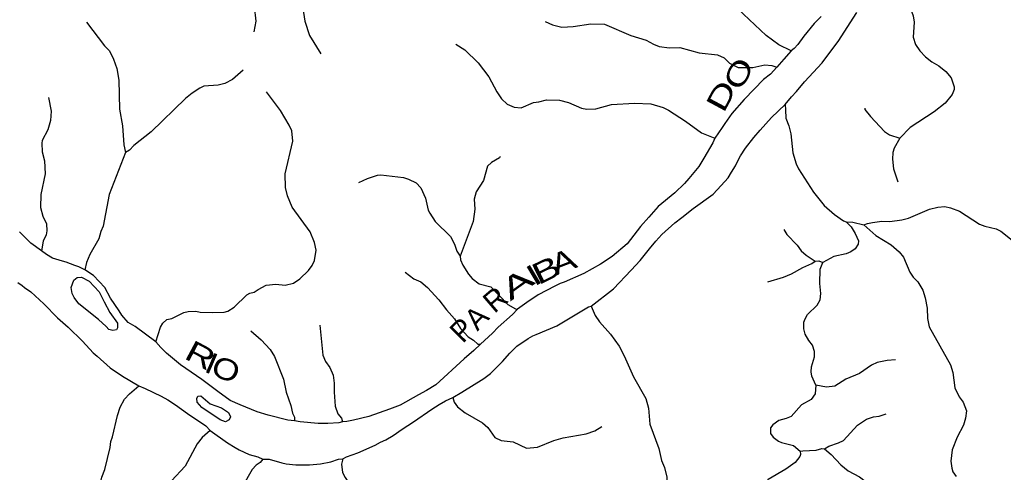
# Model space of a CAD drawing. Extents: x 577 to 602.9, y 7483.8 to 7511.6.
# Drawn here: x 584.92 to 589.586, y 7506.321 to 7508.468 of the extents above; entities that cross this region are included whole.
import ezdxf
from ezdxf.enums import TextEntityAlignment as Align

# ---------------------------------------------------------------- set-up
doc = ezdxf.new("R2010")
doc.units = 0
doc.header["$LTSCALE"] = 0.032
doc.layers.add('2', color=7, linetype='Continuous', lineweight=25)
doc.layers.add('7', color=7, linetype='Continuous', lineweight=25)
doc.layers.add('61', color=7, linetype='Continuous')

msp = doc.modelspace()

# ---------------------------------------------------------------- linework, layer by layer
at = {"layer": '2'}
for points in [[(588.7211, 7508.483), (588.6892, 7508.4503), (588.6402, 7508.3898), (588.6107, 7508.3505), (588.5936, 7508.3309), (588.5797, 7508.3203), (588.5453, 7508.2802), (588.511, 7508.2435), (588.4808, 7508.2091), (588.4489, 7508.1838), (588.4031, 7508.138), (588.3565, 7508.0898), (588.2977, 7508.0236), (588.2642, 7507.9762), (588.2519, 7507.9565), (588.2167, 7507.9059), (588.2077, 7507.8846), (588.1644, 7507.8119), (588.1407, 7507.7718), (588.0933, 7507.7146), (588.0729, 7507.6909), (588.0279, 7507.6476), (587.9486, 7507.5814), (587.9037, 7507.5315), (587.8653, 7507.4865), (587.8015, 7507.4048), (587.7296, 7507.3451), (587.6756, 7507.3092), (587.5963, 7507.265), (587.5031, 7507.2225), (587.4843, 7507.2168), (587.459, 7507.2037), (587.3797, 7507.1637), (587.325, 7507.1269), (587.2808, 7507.0958), (587.2579, 7507.0697), (587.1893, 7507.01), (587.1623, 7506.9814), (587.1051, 7506.9291), (587.0748, 7506.8996), (587.029, 7506.8596), (586.8934, 7506.737), (586.8492, 7506.71), (586.8116, 7506.6896), (586.725, 7506.6405), (586.6743, 7506.6209), (586.5762, 7506.5866), (586.5035, 7506.5686), (586.4724, 7506.562), (586.4511, 7506.5612), (586.434, 7506.5563), (586.3825, 7506.5522), (586.3359, 7506.5522), (586.2509, 7506.5604), (586.2239, 7506.5661), (586.192, 7506.5686), (586.0988, 7506.5931), (586.0473, 7506.6086), (585.9664, 7506.6422), (585.919, 7506.6626), (585.8602, 7506.7043), (585.8283, 7506.728), (585.7841, 7506.7623), (585.6828, 7506.831), (585.6166, 7506.8857), (585.5896, 7506.9127), (585.5667, 7506.9405), (585.4686, 7507.0124), (585.4351, 7507.0312), (585.404, 7507.0672), (585.3918, 7507.0868), (585.3509, 7507.1473), (585.3248, 7507.198), (585.2708, 7507.2552), (585.2299, 7507.2822), (585.2005, 7507.2953), (585.1825, 7507.3018), (585.14, 7507.3181), (585.1229, 7507.3231), (585.0763, 7507.3378), (585.0468, 7507.3541), (585.0239, 7507.3721), (584.9733, 7507.4081), (584.9185, 7507.4612)], [(586.2304, 7506.3569), (586.2942, 7506.3561), (586.3473, 7506.361), (586.3964, 7506.3716), (586.4323, 7506.3839), (586.4528, 7506.3847), (586.4699, 7506.3953), (586.5247, 7506.4133), (586.6064, 7506.4501), (586.6318, 7506.464), (586.6563, 7506.4754), (586.6923, 7506.4958), (586.734, 7506.5261), (586.7887, 7506.5612), (586.8754, 7506.6201), (586.9105, 7506.643), (586.94, 7506.6601), (586.9751, 7506.6757), (587.0168, 7506.7018), (587.1222, 7506.7664), (587.1533, 7506.7901), (587.2097, 7506.8465), (587.2448, 7506.8857), (587.2784, 7506.9193), (587.3315, 7506.956), (587.3544, 7506.9683), (587.3699, 7506.9748), (587.4672, 7507.0163), (587.6176, 7507.1064), (587.6307, 7507.1097), (587.7361, 7507.1923), (587.8211, 7507.2805), (587.8636, 7507.3263), (587.9078, 7507.3819), (587.9372, 7507.4179), (587.9658, 7507.4489), (588.0279, 7507.5045), (588.0606, 7507.5299), (588.1146, 7507.5724), (588.2094, 7507.6402), (588.2478, 7507.6811), (588.2813, 7507.7179), (588.2968, 7507.7448), (588.3148, 7507.7743), (588.3263, 7507.7988), (588.3394, 7507.8217), (588.3622, 7507.8585), (588.4023, 7507.91), (588.4317, 7507.9443), (588.4865, 7508.0048), (588.5516, 7508.066), (588.5813, 7508.102), (588.6043, 7508.1276), (588.6426, 7508.174), (588.7268, 7508.2639), (588.7489, 7508.2941), (588.8028, 7508.3652), (588.8903, 7508.5018)], [(584.9118, 7507.2219), (584.9314, 7507.2071), (584.9426, 7507.1973), (584.9725, 7507.1776), (585.0346, 7507.1203), (585.0992, 7507.0541), (585.1498, 7507.01), (585.2185, 7506.943), (585.2684, 7506.8882), (585.2872, 7506.8718), (585.3501, 7506.8163), (585.4081, 7506.777), (585.4852, 7506.7311), (585.5148, 7506.7183), (585.592, 7506.683), (585.6223, 7506.665), (585.6591, 7506.6413), (585.7163, 7506.5996), (585.8038, 7506.5416), (585.8234, 7506.5204), (585.9051, 7506.4607), (585.9427, 7506.4386), (585.9607, 7506.4272), (586.0089, 7506.4059), (586.049, 7506.3953), (586.0727, 7506.3839), (586.1037, 7506.383), (586.1634, 7506.3667), (586.1847, 7506.361), (586.2304, 7506.3569)]]:
    msp.add_lwpolyline(points, dxfattribs=at)
for points in [[(585.1784, 7507.1498), (585.1686, 7507.1702), (585.1645, 7507.198), (585.1768, 7507.2323), (585.1932, 7507.2446), (585.2136, 7507.2462), (585.2496, 7507.2282), (585.2978, 7507.1767), (585.3215, 7507.1301), (585.3476, 7507.0786), (585.3836, 7507.028), (585.3844, 7507.0059), (585.3795, 7506.9977), (585.3615, 7506.9936), (585.3436, 7506.9985), (585.3305, 7507.0133), (585.2945, 7507.046), (585.2013, 7507.1203)], [(585.8781, 7506.6274), (585.91, 7506.6054), (585.9198, 7506.5849), (585.9141, 7506.571), (585.8969, 7506.5612), (585.8716, 7506.5702), (585.7843, 7506.6286), (585.7627, 7506.6534), (585.7601, 7506.6712), (585.7646, 7506.6833), (585.7793, 7506.6839), (585.8234, 7506.6462)]]:
    msp.add_lwpolyline(points, close=True, dxfattribs=at)
at = {"layer": '7'}
for points in [[(588.5797, 7508.3203), (588.5208, 7508.3481), (588.4611, 7508.393), (588.3001, 7508.5443), (588.2454, 7508.5761), (588.2045, 7508.5859), (588.162, 7508.6039), (588.1334, 7508.6342), (588.1268, 7508.6546), (588.1072, 7508.6898), (588.086, 7508.7086), (588.0484, 7508.7331), (588.023, 7508.7601), (587.9952, 7508.8009)], [(586.2631, 7508.7061), (586.2656, 7508.6963), (586.2631, 7508.5884), (586.2582, 7508.5524), (586.2721, 7508.4609), (586.2942, 7508.3939), (586.3478, 7508.3065)], [(589.0212, 7508.7066), (589.026, 7508.6742), (589.0391, 7508.6383), (589.1175, 7508.5622), (589.142, 7508.5295), (589.1584, 7508.4862), (589.1633, 7508.456), (589.1584, 7508.3857), (589.169, 7508.3505), (589.1895, 7508.3203), (589.2164, 7508.2917), (589.2467, 7508.2688), (589.2802, 7508.25), (589.3137, 7508.223), (589.3382, 7508.1928), (589.3529, 7508.1495), (589.3521, 7508.1364), (589.3431, 7508.1135), (589.3104, 7508.0718), (589.2581, 7508.0309), (589.1437, 7507.9574), (589.0946, 7507.9067)], [(586.0866, 7508.675), (586.0792, 7508.6579), (586.0596, 7508.6358), (586.0482, 7508.6146), (586.0367, 7508.572), (586.0326, 7508.5304), (586.0408, 7508.4617), (586.0302, 7508.4109)], [(585.2374, 7508.4571), (585.3223, 7508.3448), (585.346, 7508.3203), (585.3656, 7508.2802), (585.3803, 7508.2369), (585.391, 7508.1813), (585.3934, 7508.044), (585.4081, 7507.9647), (585.4147, 7507.874), (585.422, 7507.8388)], [(587.4121, 7508.46), (587.4476, 7508.4437), (587.4909, 7508.4331), (587.5448, 7508.4355), (587.629, 7508.4478), (587.6944, 7508.4462), (587.8187, 7508.3939), (587.8922, 7508.371), (587.9266, 7508.3513), (587.9527, 7508.3415), (588.0018, 7508.335), (588.0516, 7508.3358), (588.1424, 7508.3105), (588.2298, 7508.3007), (588.2609, 7508.2876), (588.2869, 7508.2615), (588.3276, 7508.242), (588.3982, 7508.2418), (588.4546, 7508.2533), (588.4881, 7508.2516), (588.511, 7508.2435)], [(586.9884, 7508.3525), (587.0315, 7508.3244), (587.0953, 7508.2631), (587.1459, 7508.1977), (587.1835, 7508.1257), (587.2048, 7508.093), (587.2318, 7508.0669), (587.2661, 7508.0538), (587.298, 7508.0505), (587.3568, 7508.0751), (587.3822, 7508.0792), (587.4181, 7508.0873), (587.4811, 7508.0857), (587.5228, 7508.0759), (587.5849, 7508.0481), (587.6094, 7508.044), (587.6535, 7508.0456), (587.7271, 7508.0661), (587.8366, 7508.0726), (587.9135, 7508.0685), (587.9715, 7508.0522), (587.9977, 7508.0391), (588.0786, 7507.9868), (588.1546, 7507.9312), (588.2167, 7507.9059)], [(585.9798, 7508.2282), (585.9288, 7508.1838), (585.8937, 7508.1658), (585.861, 7508.1576), (585.7939, 7508.1527), (585.7743, 7508.1437), (585.7384, 7508.1192), (585.7073, 7508.0947), (585.5438, 7507.9361), (585.4621, 7507.8707), (585.4408, 7507.8495), (585.422, 7507.8388)], [(585.0567, 7508.0987), (585.0689, 7508.035), (585.0665, 7507.9892), (585.0534, 7507.9459), (585.0264, 7507.8944), (585.0256, 7507.8822), (585.0272, 7507.8421), (585.0378, 7507.798), (585.0403, 7507.7367), (585.0207, 7507.6394), (585.019, 7507.5773), (585.0305, 7507.5356), (585.0468, 7507.4996), (585.0485, 7507.4669), (585.0452, 7507.4481), (585.0313, 7507.4171), (585.0239, 7507.3721)], [(585.5667, 7506.9405), (585.588, 7507.0092), (585.5986, 7507.028), (585.6182, 7507.046), (585.6411, 7507.0509), (585.6991, 7507.0795), (585.7196, 7507.0844), (585.7555, 7507.086), (585.776, 7507.0811), (585.8332, 7507.0786), (585.8904, 7507.0803), (585.9067, 7507.0852), (585.9378, 7507.104), (585.9983, 7507.1637), (586.0122, 7507.1718), (586.0326, 7507.1751), (586.0514, 7507.189), (586.0898, 7507.2086), (586.1348, 7507.2135), (586.1798, 7507.2086), (586.219, 7507.2184), (586.2492, 7507.2397), (586.2901, 7507.2781), (586.3073, 7507.3018), (586.3187, 7507.3255), (586.3269, 7507.3745), (586.3187, 7507.4121), (586.2975, 7507.462), (586.2125, 7507.5797), (586.1904, 7507.6328), (586.1814, 7507.6721), (586.1798, 7507.7375), (586.2165, 7507.892), (586.2108, 7507.941), (586.1986, 7507.968), (586.1569, 7508.0375), (586.0908, 7508.1253)], [(588.5516, 7508.066), (588.5519, 7508.0407), (588.5535, 7508.0015), (588.5682, 7507.9647), (588.578, 7507.9271), (588.5878, 7507.8372), (588.6026, 7507.7841), (588.614, 7507.7604), (588.6859, 7507.65), (588.7366, 7507.5871), (588.7848, 7507.5438), (588.8273, 7507.5135), (588.8396, 7507.5086)], [(588.9286, 7508.0481), (588.9295, 7508.0416), (588.9549, 7508.0089), (589.0219, 7507.9377), (589.0456, 7507.9214), (589.0946, 7507.9067)], [(589.0946, 7507.9067), (589.0677, 7507.8593), (589.0619, 7507.838), (589.0595, 7507.807), (589.0644, 7507.7604), (589.0853, 7507.6985)], [(585.422, 7507.8388), (585.3452, 7507.6386), (585.3166, 7507.489), (585.3051, 7507.4636), (585.2953, 7507.4285), (585.2534, 7507.3548), (585.237, 7507.3165), (585.2299, 7507.2822)], [(587.1992, 7507.8196), (587.1966, 7507.8135), (587.1574, 7507.7914), (587.1386, 7507.7734), (587.1198, 7507.7056), (587.0846, 7507.6516), (587.0756, 7507.6165), (587.0797, 7507.5699), (587.0707, 7507.5111), (587.0094, 7507.3468)], [(586.5284, 7507.6964), (586.5697, 7507.7154), (586.6171, 7507.7309), (586.6334, 7507.7318), (586.7405, 7507.7203), (586.765, 7507.7121), (586.801, 7507.6942), (586.8222, 7507.6704), (586.8451, 7507.6214), (586.8582, 7507.5642), (586.8656, 7507.5503), (586.8909, 7507.5111), (586.9637, 7507.4391), (586.9825, 7507.404), (586.9939, 7507.3705), (587.0094, 7507.3468)], [(588.9246, 7507.4947), (588.941, 7507.5021), (588.9647, 7507.5062), (589.0096, 7507.5119), (589.0472, 7507.5111), (589.1036, 7507.5184), (589.1355, 7507.5266), (589.2352, 7507.5691), (589.2745, 7507.5797), (589.3088, 7507.5814), (589.335, 7507.5764), (589.3783, 7507.5601), (589.4731, 7507.498), (589.4984, 7507.4882), (589.5524, 7507.4759), (589.5736, 7507.4653), (589.6276, 7507.422), (589.6725, 7507.3721), (589.6979, 7507.35), (589.7759, 7507.3057)], [(588.8396, 7507.5086), (588.8641, 7507.4857), (588.8837, 7507.4538), (588.8985, 7507.4187), (588.8976, 7507.404), (588.8829, 7507.3819), (588.8625, 7507.3672), (588.8396, 7507.3574), (588.7824, 7507.3443), (588.7301, 7507.3165)], [(588.8396, 7507.5086), (588.8715, 7507.507), (588.9246, 7507.4947)], [(588.9246, 7507.4947), (588.9802, 7507.4448), (589.0538, 7507.3999), (589.0922, 7507.3664), (589.1118, 7507.3419), (589.142, 7507.2707), (589.1584, 7507.2462), (589.1796, 7507.2241), (589.2042, 7507.1849), (589.2156, 7507.1489), (589.2238, 7507.0999), (589.2254, 7507.0509), (589.2336, 7507.0108), (589.335, 7506.8318), (589.3464, 7506.7942), (589.3562, 7506.7214), (589.3766, 7506.6798), (589.3946, 7506.6544), (589.411, 7506.6127), (589.4069, 7506.5784), (589.3971, 7506.5457), (589.3668, 7506.4877), (589.3431, 7506.428), (589.3366, 7506.3749), (589.3407, 7506.3413), (589.3464, 7506.3242), (589.3619, 7506.3021)], [(588.5441, 7507.4724), (588.5592, 7507.4498), (588.6075, 7507.3991), (588.6263, 7507.3721), (588.6508, 7507.3508), (588.6933, 7507.3231)], [(587.0094, 7507.3468), (587.0111, 7507.3288), (587.0217, 7507.3034), (587.0487, 7507.2609), (587.0666, 7507.2405), (587.0993, 7507.2152), (587.1549, 7507.2013), (587.2359, 7507.1179), (587.2726, 7507.0966), (587.2808, 7507.0958)], [(588.4692, 7507.2246), (588.5429, 7507.2462), (588.5813, 7507.2626), (588.6344, 7507.2928), (588.6778, 7507.3116), (588.6933, 7507.3231)], [(588.6957, 7506.7353), (588.6778, 7506.777), (588.6745, 7506.7975), (588.6753, 7506.822), (588.69, 7506.8694), (588.6908, 7506.8947), (588.681, 7506.925), (588.663, 7506.9462), (588.6451, 7506.9773), (588.6402, 7507.0026), (588.6402, 7507.0337), (588.6451, 7507.05), (588.6573, 7507.0705), (588.7023, 7507.1138), (588.7162, 7507.1391), (588.7194, 7507.1694), (588.7154, 7507.2168), (588.7162, 7507.2855), (588.7301, 7507.3165)], [(588.6933, 7507.3231), (588.7113, 7507.3239), (588.7301, 7507.3165)], [(586.7493, 7507.2707), (586.7904, 7507.2397), (586.8222, 7507.2241), (586.8549, 7507.1972), (586.9089, 7507.14), (586.944, 7507.0917), (586.9825, 7507.0492), (587.0102, 7507.0034), (587.0478, 7506.9634), (587.0724, 7506.9487), (587.0928, 7506.9299), (587.1051, 7506.9291)], [(587.6307, 7507.1097), (587.6503, 7507.0656), (587.6699, 7507.0353), (587.7222, 7506.9765), (587.7639, 7506.9193), (587.7876, 7506.8743), (587.8309, 7506.7738), (587.8898, 7506.6708), (587.9029, 7506.6258), (587.9094, 7506.5498), (587.9519, 7506.4345), (587.9642, 7506.3773), (587.9781, 7506.3446), (587.9903, 7506.2988), (587.9911, 7506.2294), (587.9864, 7506.1992)], [(586.3444, 7507.0185), (586.358, 7506.8776), (586.3702, 7506.8473), (586.3915, 7506.8179), (586.407, 7506.7827), (586.4119, 7506.7443), (586.4111, 7506.7018), (586.4168, 7506.6356), (586.4299, 7506.5988), (586.4462, 7506.5776), (586.4511, 7506.5612)], [(586.0169, 7506.9929), (586.0653, 7506.9503), (586.1078, 7506.9045), (586.1291, 7506.871), (586.1716, 7506.7631), (586.1847, 7506.701), (586.2059, 7506.6389), (586.2141, 7506.6013), (586.2231, 7506.5825), (586.2239, 7506.5661)], [(589.0746, 7506.8547), (589.0341, 7506.8522), (588.9867, 7506.8424), (588.9606, 7506.8293), (588.9042, 7506.7901), (588.8388, 7506.7639), (588.7857, 7506.7296), (588.7464, 7506.7247), (588.6957, 7506.7353)], [(584.9299, 7505.7035), (584.9839, 7505.7822), (585.1457, 7505.9474), (585.1858, 7506.0005), (585.2528, 7506.1337), (585.297, 7506.2433), (585.31, 7506.2988), (585.3248, 7506.3348), (585.3493, 7506.4394), (585.3525, 7506.4672), (585.3607, 7506.4901), (585.3836, 7506.5915), (585.3967, 7506.6299), (585.4179, 7506.6683), (585.4409, 7506.6938), (585.4852, 7506.7311)], [(588.6957, 7506.7353), (588.6925, 7506.6928), (588.6737, 7506.6667), (588.6287, 7506.6413), (588.5789, 7506.5866), (588.556, 7506.5759), (588.5216, 7506.5678), (588.493, 7506.5465), (588.4816, 7506.5318), (588.4808, 7506.5056), (588.4947, 7506.4877), (588.5192, 7506.4689), (588.5339, 7506.4623), (588.5903, 7506.4484), (588.6214, 7506.4223)], [(586.9751, 7506.6757), (586.9808, 7506.6536), (586.9964, 7506.6323), (587.0331, 7506.6037), (587.1149, 7506.5563), (587.1402, 7506.5334), (587.1745, 7506.4868), (587.2032, 7506.4729), (587.2612, 7506.4656), (587.3233, 7506.4353), (587.3764, 7506.4411), (587.4541, 7506.4729), (587.4982, 7506.4852), (587.607, 7506.5032), (587.6478, 7506.5179), (587.6817, 7506.5386)], [(588.7374, 7506.4329), (588.7587, 7506.446), (588.8036, 7506.4607), (588.8273, 7506.4729), (588.8944, 7506.5449), (588.9361, 7506.5735), (588.9704, 7506.5849), (588.9974, 7506.5882), (589.0299, 7506.5984)], [(585.8234, 7506.5204), (585.785, 7506.4868), (585.7621, 7506.4558), (585.7057, 7506.3503), (585.6395, 7506.2809), (585.6207, 7506.2457), (585.6002, 7506.1926), (585.5128, 7506.0152), (585.4948, 7505.9457), (585.4686, 7505.797), (585.4653, 7505.7561), (585.4539, 7505.7119), (585.4523, 7505.6498), (585.4555, 7505.6253), (585.4784, 7505.5387), (585.4817, 7505.5133), (585.4801, 7505.4716), (585.4735, 7505.443), (585.458, 7505.4079), (585.4531, 7505.4005), (585.4478, 7505.3996)], [(588.6214, 7506.4223), (588.6238, 7506.4051), (588.6205, 7506.3969), (588.5985, 7506.3675), (588.5535, 7506.3364), (588.471, 7506.2874), (588.4472, 7506.2629)], [(588.6214, 7506.4223), (588.6344, 7506.4231), (588.6982, 7506.4264), (588.7244, 7506.4337), (588.7374, 7506.4329)], [(588.7374, 7506.4329), (588.7693, 7506.4051), (588.8151, 7506.3561), (588.8494, 7506.3291), (588.9034, 7506.2997), (588.9707, 7506.2475)], [(586.0727, 7506.3839), (586.0604, 7506.3683), (586.0424, 7506.3552), (586.0236, 7506.3348), (585.977, 7506.2539), (585.9566, 7506.2089), (585.9329, 7506.1337), (585.8577, 7505.976), (585.8414, 7505.949), (585.8201, 7505.8525), (585.8029, 7505.8059), (585.7882, 7505.7871), (585.7792, 7505.7675), (585.7644, 7505.7072)], [(586.4528, 7506.3847), (586.4471, 7506.3601), (586.452, 7506.3201), (586.4634, 7506.2964), (586.4814, 7506.271), (586.5337, 7506.2146), (586.5876, 7506.1672), (586.6449, 7506.0912), (586.6972, 7506.0356), (586.8018, 7505.9392)]]:
    msp.add_lwpolyline(points, dxfattribs=at)

# ---------------------------------------------------------------- texts
at = {"layer": '61'}
for s, rotation, width, p in [('O', 62.354, 1.4, (588.3741, 7508.1894)), ('D', 61.795, 1.45, (588.2918, 7508.0831)), ('B', 25.962, 1.45, (587.4389, 7507.2365)), ('A', 21.087, 1.3, (587.5169, 7507.2746)), ('I', 30.837, 1.45, (587.3838, 7507.2141)), ('A', 35.711, 1.7, (587.3084, 7507.1751)), ('R', 331.841, 1.4, (585.7546, 7506.8323)), ('I', 336.585, 1.2, (585.8107, 7506.7923)), ('O', 338.528, 1.25, (585.8805, 7506.7632))]:
    msp.add_text(s, height=0.1, rotation=rotation, dxfattribs=dict(at, width=width)).set_placement(p, align=Align.CENTER)
for s, rotation, p in [('R', 40.586, (587.2084, 7507.1031)), ('A', 45.461, (587.1224, 7507.0199)), ('P', 45.461, (587.0528, 7506.9617))]:
    msp.add_text(s, height=0.1, rotation=rotation, dxfattribs=at).set_placement(p, align=Align.CENTER)

doc.saveas('drawing.dxf')
